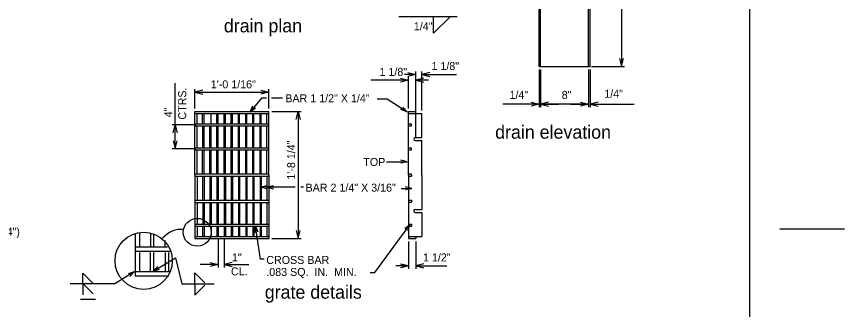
# Model space of a CAD drawing. Extents: x 973.2 to 1069.7, y 1484.4 to 1549.5.
# Drawn here: x 1034.82 to 1069.31, y 1513.03 to 1525.25 of the extents above; entities that cross this region are included whole.
import ezdxf

# ---------------------------------------------------------------- set-up
doc = ezdxf.new("R2010")
doc.units = 0
for name, color, linetype in [('Level 1', 7, 'Continuous'), ('Level 2', 7, 'Continuous'), ('Level 37', 7, 'Continuous')]:
    doc.layers.add(name, color=color, linetype=linetype)

msp = doc.modelspace()

# ---------------------------------------------------------------- linework, layer by layer
at = {"layer": 'Level 1'}
msp.add_line((1065.368, 1488.431), (1065.368, 1544.364), dxfattribs=at)
at = {"layer": 'Level 2'}
for p, q in [((1058.651, 1523.167), (1058.651, 1536.917)), ((1058.713, 1523.17), (1058.713, 1536.917)), ((1056.588, 1523.17), (1056.588, 1535.381)), ((1056.651, 1523.167), (1056.651, 1535.414)), ((1060.017, 1530.323), (1060.017, 1523.167)), ((1050.748, 1525.244), (1053.178, 1525.244)), ((1052.196, 1524.548), (1052.892, 1525.244)), ((1052.196, 1524.548), (1052.196, 1525.212)), ((1051.45, 1520.233), (1051.45, 1522.962)), ((1051.709, 1521.325), (1051.709, 1522.962)), ((1056.588, 1523.17), (1058.713, 1523.17)), ((1056.588, 1523.045), (1056.588, 1521.473)), ((1056.651, 1523.042), (1056.651, 1521.473)), ((1058.651, 1523.042), (1058.651, 1521.473)), ((1058.713, 1523.045), (1058.713, 1521.473)), ((1058.776, 1523.167), (1060.142, 1523.167)), ((1051.147, 1522.591), (1049.575, 1522.591)), ((1051.45, 1522.837), (1050.976, 1522.837)), ((1051.147, 1521.414), (1051.147, 1522.761)), ((1051.976, 1522.591), (1051.45, 1522.591)), ((1051.709, 1522.837), (1053.141, 1522.837)), ((1041.428, 1519.726), (1041.428, 1522.467)), ((1042.251, 1521.414), (1042.251, 1522.22)), ((1045.329, 1521.414), (1045.329, 1522.22)), ((1042.251, 1522.095), (1045.329, 1522.095)), ((1045.022, 1521.85), (1044.551, 1521.277)), ((1045.234, 1521.85), (1045.022, 1521.85)), ((1045.896, 1521.85), (1045.444, 1521.85)), ((1044.551, 1521.277), (1044.666, 1521.519)), ((1049.849, 1521.813), (1050.265, 1521.813)), ((1050.265, 1521.813), (1051.088, 1521.277)), ((1056.588, 1521.597), (1055.08, 1521.597)), ((1058.651, 1521.597), (1056.651, 1521.597)), ((1056.651, 1521.597), (1057.401, 1521.597)), ((1057.901, 1521.597), (1058.651, 1521.597)), ((1058.713, 1521.597), (1060.556, 1521.597)), ((1042.251, 1518.637), (1042.251, 1521.289)), ((1042.251, 1521.289), (1045.329, 1521.289)), ((1042.251, 1521.2), (1045.329, 1521.2)), ((1042.342, 1520.8), (1042.342, 1521.2)), ((1042.566, 1520.8), (1042.566, 1521.2)), ((1042.631, 1520.8), (1042.631, 1521.2)), ((1042.922, 1520.8), (1042.922, 1521.2)), ((1043.166, 1520.8), (1043.166, 1521.2)), ((1043.219, 1520.8), (1043.219, 1521.2)), ((1043.466, 1520.8), (1043.466, 1521.2)), ((1043.522, 1520.8), (1043.522, 1521.2)), ((1043.756, 1520.8), (1043.756, 1521.2)), ((1043.809, 1520.8), (1043.809, 1521.2)), ((1044.062, 1520.8), (1044.062, 1521.2)), ((1044.109, 1520.8), (1044.109, 1521.2)), ((1044.365, 1520.8), (1044.365, 1521.2)), ((1044.409, 1520.8), (1044.409, 1521.2)), ((1044.551, 1521.277), (1044.767, 1521.436)), ((1044.665, 1520.8), (1044.665, 1521.2)), ((1044.703, 1520.8), (1044.703, 1521.2)), ((1044.962, 1520.8), (1044.962, 1521.2)), ((1045.009, 1520.8), (1045.009, 1521.2)), ((1045.248, 1520.8), (1045.248, 1521.2)), ((1045.329, 1518.637), (1045.329, 1521.289)), ((1045.454, 1521.289), (1046.674, 1521.289)), ((1046.548, 1521.289), (1046.548, 1515.985)), ((1051.088, 1521.277), (1050.835, 1521.364)), ((1051.088, 1521.277), (1050.906, 1521.473)), ((1051.147, 1518.637), (1051.147, 1521.289)), ((1051.147, 1521.289), (1051.454, 1521.289)), ((1051.147, 1521.2), (1051.709, 1521.2)), ((1051.454, 1521.2), (1051.454, 1521.289)), ((1051.709, 1520.2), (1051.709, 1521.2)), ((1042.305, 1520.736), (1041.303, 1520.736)), ((1042.251, 1520.776), (1045.329, 1520.776)), ((1042.251, 1520.683), (1045.329, 1520.683)), ((1042.342, 1519.788), (1042.342, 1520.676)), ((1042.572, 1519.788), (1042.572, 1520.676)), ((1042.631, 1519.788), (1042.631, 1520.676)), ((1042.875, 1519.788), (1042.875, 1520.676)), ((1042.922, 1519.788), (1042.922, 1520.676)), ((1043.166, 1519.788), (1043.166, 1520.676)), ((1043.219, 1519.788), (1043.219, 1520.676)), ((1043.466, 1519.788), (1043.466, 1520.676)), ((1043.519, 1519.788), (1043.519, 1520.676)), ((1043.756, 1519.788), (1043.756, 1520.676)), ((1043.809, 1519.788), (1043.809, 1520.676)), ((1044.062, 1519.788), (1044.062, 1520.676)), ((1044.109, 1519.788), (1044.109, 1520.676)), ((1044.365, 1519.788), (1044.365, 1520.676)), ((1044.409, 1519.788), (1044.409, 1520.676)), ((1044.665, 1519.788), (1044.665, 1520.676)), ((1044.703, 1519.788), (1044.703, 1520.676)), ((1044.962, 1519.788), (1044.962, 1520.676)), ((1045.009, 1519.788), (1045.009, 1520.676)), ((1045.248, 1519.788), (1045.248, 1520.676)), ((1051.147, 1520.776), (1051.268, 1520.776)), ((1051.147, 1520.685), (1051.268, 1520.685)), ((1051.268, 1520.685), (1051.268, 1520.776)), ((1042.305, 1520.313), (1042.305, 1520.313)), ((1042.602, 1520.312), (1042.602, 1520.312)), ((1042.9, 1520.311), (1042.9, 1520.311)), ((1043.197, 1520.309), (1043.197, 1520.309)), ((1043.495, 1520.308), (1043.495, 1520.308)), ((1043.792, 1520.307), (1043.792, 1520.307)), ((1044.089, 1520.306), (1044.089, 1520.306)), ((1044.387, 1520.304), (1044.387, 1520.304)), ((1044.684, 1520.303), (1044.684, 1520.303)), ((1044.982, 1520.302), (1044.982, 1520.302)), ((1045.279, 1520.301), (1045.279, 1520.301)), ((1051.434, 1520.2), (1051.709, 1520.2)), ((1042.251, 1519.776), (1045.329, 1519.776)), ((1051.434, 1520.075), (1051.709, 1520.075)), ((1051.709, 1518.637), (1051.709, 1520.075)), ((1042.279, 1519.726), (1041.303, 1519.726)), ((1042.251, 1519.683), (1045.329, 1519.683)), ((1042.342, 1518.708), (1042.342, 1519.676)), ((1042.566, 1518.708), (1042.566, 1519.676)), ((1042.631, 1518.708), (1042.631, 1519.676)), ((1042.875, 1518.708), (1042.875, 1519.676)), ((1042.922, 1518.708), (1042.922, 1519.676)), ((1043.166, 1518.708), (1043.166, 1519.676)), ((1043.219, 1518.708), (1043.219, 1519.676)), ((1043.466, 1518.708), (1043.466, 1519.676)), ((1043.519, 1518.708), (1043.519, 1519.676)), ((1043.756, 1518.708), (1043.756, 1519.676)), ((1043.809, 1518.708), (1043.809, 1519.676)), ((1044.062, 1518.708), (1044.062, 1519.676)), ((1044.109, 1518.708), (1044.109, 1519.676)), ((1044.365, 1518.708), (1044.365, 1519.676)), ((1044.409, 1518.708), (1044.409, 1519.676)), ((1044.665, 1518.708), (1044.665, 1519.676)), ((1044.703, 1518.708), (1044.703, 1519.676)), ((1044.962, 1518.708), (1044.962, 1519.676)), ((1045.009, 1518.708), (1045.009, 1519.676)), ((1045.248, 1518.708), (1045.248, 1519.676)), ((1051.147, 1519.768), (1051.268, 1519.768)), ((1051.147, 1519.692), (1051.268, 1519.692)), ((1051.268, 1519.692), (1051.268, 1519.768)), ((1050.232, 1519.191), (1051.09, 1519.191)), ((1051.09, 1519.191), (1050.83, 1519.256)), ((1051.09, 1519.191), (1050.83, 1519.126)), ((1042.251, 1518.683), (1045.329, 1518.683)), ((1042.251, 1518.637), (1042.251, 1515.985)), ((1042.251, 1518.592), (1045.329, 1518.592)), ((1042.342, 1518.567), (1042.342, 1517.598)), ((1042.566, 1518.567), (1042.566, 1517.598)), ((1042.631, 1518.567), (1042.631, 1517.598)), ((1042.875, 1518.567), (1042.875, 1517.598)), ((1042.922, 1518.567), (1042.922, 1517.598)), ((1043.166, 1518.567), (1043.166, 1517.598)), ((1043.219, 1518.567), (1043.219, 1517.598)), ((1043.466, 1518.567), (1043.466, 1517.598)), ((1043.519, 1518.567), (1043.519, 1517.598)), ((1043.756, 1518.567), (1043.756, 1517.598)), ((1043.809, 1518.567), (1043.809, 1517.598)), ((1044.062, 1518.567), (1044.062, 1517.598)), ((1044.109, 1518.567), (1044.109, 1517.598)), ((1044.365, 1518.567), (1044.365, 1517.598)), ((1044.409, 1518.567), (1044.409, 1517.598)), ((1044.665, 1518.567), (1044.665, 1517.598)), ((1044.703, 1518.567), (1044.703, 1517.598)), ((1044.962, 1518.567), (1044.962, 1517.598)), ((1045.009, 1518.567), (1045.009, 1517.598)), ((1045.248, 1518.567), (1045.248, 1517.598)), ((1045.329, 1518.637), (1045.329, 1515.985)), ((1051.147, 1518.683), (1051.268, 1518.683)), ((1051.147, 1518.637), (1051.147, 1515.985)), ((1051.147, 1518.592), (1051.268, 1518.592)), ((1051.268, 1518.637), (1051.268, 1518.683)), ((1051.268, 1518.637), (1051.268, 1518.592)), ((1051.709, 1518.637), (1051.709, 1517.199)), ((1044.998, 1518.148), (1045.262, 1518.194)), ((1045.259, 1518.129), (1044.998, 1518.148)), ((1044.998, 1518.148), (1045.253, 1518.065)), ((1045.259, 1518.129), (1045.519, 1518.194)), ((1045.259, 1518.129), (1045.519, 1518.064)), ((1046.432, 1518.129), (1045.259, 1518.129)), ((1046.773, 1518.129), (1046.656, 1518.129)), ((1050.847, 1518.08), (1051.286, 1518.08)), ((1051.286, 1518.08), (1051.026, 1518.145)), ((1051.286, 1518.08), (1051.026, 1518.015)), ((1042.251, 1517.592), (1045.329, 1517.592)), ((1042.251, 1517.498), (1045.329, 1517.498)), ((1042.342, 1517.486), (1042.342, 1516.599)), ((1042.572, 1517.486), (1042.572, 1516.599)), ((1042.631, 1517.486), (1042.631, 1516.599)), ((1042.875, 1517.486), (1042.875, 1516.599)), ((1042.922, 1517.486), (1042.922, 1516.599)), ((1043.166, 1517.486), (1043.166, 1516.599)), ((1043.219, 1517.486), (1043.219, 1516.599)), ((1043.466, 1517.486), (1043.466, 1516.599)), ((1043.519, 1517.486), (1043.519, 1516.599)), ((1043.756, 1517.486), (1043.756, 1516.599)), ((1043.809, 1517.486), (1043.809, 1516.599)), ((1044.062, 1517.486), (1044.062, 1516.599)), ((1044.109, 1517.486), (1044.109, 1516.599)), ((1044.365, 1517.486), (1044.365, 1516.599)), ((1044.409, 1517.486), (1044.409, 1516.599)), ((1044.665, 1517.486), (1044.665, 1516.599)), ((1044.703, 1517.486), (1044.703, 1516.599)), ((1044.962, 1517.486), (1044.962, 1516.599)), ((1045.009, 1517.486), (1045.009, 1516.599)), ((1045.248, 1517.486), (1045.248, 1516.599)), ((1051.147, 1517.583), (1051.268, 1517.583)), ((1051.147, 1517.506), (1051.268, 1517.506)), ((1051.268, 1517.583), (1051.268, 1517.506)), ((1051.434, 1517.2), (1051.709, 1517.2)), ((1051.434, 1517.075), (1051.709, 1517.075)), ((1051.709, 1517.074), (1051.709, 1516.075)), ((1042.305, 1516.961), (1042.305, 1516.961)), ((1042.602, 1516.962), (1042.602, 1516.962)), ((1042.9, 1516.964), (1042.9, 1516.964)), ((1043.197, 1516.965), (1043.197, 1516.965)), ((1043.495, 1516.966), (1043.495, 1516.966)), ((1043.792, 1516.967), (1043.792, 1516.967)), ((1044.089, 1516.969), (1044.089, 1516.969)), ((1044.387, 1516.97), (1044.387, 1516.97)), ((1044.684, 1516.971), (1044.684, 1516.971)), ((1044.982, 1516.972), (1044.982, 1516.972)), ((1045.279, 1516.974), (1045.279, 1516.974)), ((1042.251, 1516.592), (1045.329, 1516.592)), ((1042.251, 1516.498), (1045.329, 1516.498)), ((1042.342, 1516.474), (1042.342, 1516.075)), ((1042.566, 1516.474), (1042.566, 1516.075)), ((1042.631, 1516.474), (1042.631, 1516.075)), ((1042.922, 1516.474), (1042.922, 1516.075)), ((1043.166, 1516.474), (1043.166, 1516.075)), ((1043.219, 1516.474), (1043.219, 1516.075)), ((1043.466, 1516.474), (1043.466, 1516.075)), ((1043.522, 1516.474), (1043.522, 1516.075)), ((1043.756, 1516.474), (1043.756, 1516.075)), ((1043.809, 1516.474), (1043.809, 1516.075)), ((1044.062, 1516.474), (1044.062, 1516.075)), ((1044.109, 1516.474), (1044.109, 1516.075)), ((1044.365, 1516.474), (1044.365, 1516.075)), ((1044.409, 1516.474), (1044.409, 1516.075)), ((1044.665, 1516.474), (1044.665, 1516.075)), ((1044.703, 1516.474), (1044.703, 1516.075)), ((1044.775, 1516.509), (1044.748, 1516.242)), ((1044.975, 1515.131), (1044.775, 1516.509)), ((1044.775, 1516.509), (1044.876, 1516.261)), ((1044.962, 1516.474), (1044.962, 1516.075)), ((1045.009, 1516.474), (1045.009, 1516.075)), ((1045.248, 1516.474), (1045.248, 1516.075)), ((1049.743, 1514.566), (1051.2, 1516.565)), ((1051.2, 1516.565), (1050.995, 1516.393)), ((1051.2, 1516.565), (1051.1, 1516.316)), ((1051.147, 1516.589), (1051.268, 1516.589)), ((1051.147, 1516.498), (1051.268, 1516.498)), ((1051.268, 1516.589), (1051.268, 1516.498)), ((1039.759, 1516.188), (1039.759, 1514.432)), ((1039.942, 1516.244), (1039.942, 1515.659)), ((1040.402, 1516.197), (1040.402, 1515.659)), ((1040.52, 1516.16), (1040.52, 1515.659)), ((1042.251, 1516.075), (1045.329, 1516.075)), ((1042.251, 1515.985), (1045.329, 1515.985)), ((1045.454, 1515.985), (1046.674, 1515.985)), ((1051.147, 1516.075), (1051.709, 1516.075)), ((1051.147, 1515.985), (1051.454, 1515.985)), ((1051.454, 1516.075), (1051.454, 1515.985)), ((1039.759, 1515.645), (1041.101, 1515.645)), ((1040.989, 1515.908), (1040.989, 1515.659)), ((1043.219, 1515.95), (1043.219, 1514.786)), ((1043.466, 1515.95), (1043.466, 1514.786)), ((1051.147, 1515.86), (1051.147, 1514.721)), ((1051.45, 1515.86), (1051.45, 1514.721)), ((1039.759, 1515.458), (1041.259, 1515.458)), ((1039.942, 1515.41), (1039.942, 1514.611)), ((1040.389, 1515.41), (1040.389, 1514.611)), ((1040.52, 1515.41), (1040.52, 1514.611)), ((1041.008, 1515.41), (1041.008, 1514.611)), ((1041.148, 1515.41), (1041.148, 1514.611)), ((1040.514, 1514.633), (1041.436, 1515.182)), ((1041.436, 1515.182), (1041.706, 1514.092)), ((1045.137, 1515.131), (1044.975, 1515.131)), ((1039.723, 1514.605), (1038.913, 1514.092)), ((1039.723, 1514.605), (1039.468, 1514.521)), ((1039.723, 1514.605), (1039.538, 1514.411)), ((1039.759, 1514.611), (1041.231, 1514.611)), ((1040.514, 1514.633), (1040.704, 1514.821)), ((1040.514, 1514.633), (1040.771, 1514.71)), ((1043.219, 1514.911), (1042.469, 1514.911)), ((1043.466, 1514.911), (1044.498, 1514.911)), ((1051.147, 1514.846), (1050.615, 1514.846)), ((1051.147, 1514.846), (1050.887, 1514.911)), ((1051.147, 1514.846), (1050.887, 1514.781)), ((1051.45, 1514.846), (1052.744, 1514.846)), ((1037.581, 1514.092), (1037.581, 1514.54)), ((1037.581, 1514.54), (1037.996, 1514.125)), ((1039.759, 1514.432), (1041.092, 1514.432)), ((1042.246, 1514.111), (1042.246, 1514.558)), ((1042.246, 1514.558), (1042.662, 1514.143)), ((1049.55, 1514.566), (1049.743, 1514.566)), ((1038.913, 1514.092), (1037.049, 1514.092)), ((1037.581, 1514.092), (1037.581, 1513.645)), ((1037.59, 1514.093), (1038.006, 1513.678)), ((1041.706, 1514.092), (1043.047, 1514.092)), ((1042.246, 1514.074), (1042.246, 1513.626)), ((1042.246, 1513.626), (1042.662, 1514.042)), ((1037.488, 1513.459), (1038.103, 1513.459))]:
    msp.add_line(p, q, dxfattribs=at)
for points in [[(1059.934, 1523.5), (1060.017, 1523.167), (1060.101, 1523.5)], [(1051.117, 1522.92), (1051.45, 1522.837), (1051.117, 1522.753)], [(1052.042, 1522.92), (1051.709, 1522.837), (1052.042, 1522.753)], [(1050.813, 1522.674), (1051.147, 1522.591), (1050.813, 1522.507)], [(1051.783, 1522.674), (1051.45, 1522.591), (1051.783, 1522.507)], [(1042.584, 1522.178), (1042.251, 1522.095), (1042.584, 1522.011)], [(1044.995, 1522.178), (1045.329, 1522.095), (1044.995, 1522.011)], [(1056.255, 1521.681), (1056.588, 1521.597), (1056.255, 1521.514)], [(1056.984, 1521.681), (1056.651, 1521.597), (1056.984, 1521.514)], [(1058.317, 1521.681), (1058.651, 1521.597), (1058.317, 1521.514)], [(1059.047, 1521.681), (1058.713, 1521.597), (1059.047, 1521.514)], [(1046.465, 1520.956), (1046.548, 1521.289), (1046.632, 1520.956)], [(1041.344, 1520.403), (1041.428, 1520.736), (1041.511, 1520.403)], [(1041.344, 1520.059), (1041.428, 1519.726), (1041.511, 1520.059)], [(1046.465, 1516.318), (1046.548, 1515.985), (1046.632, 1516.318)], [(1042.885, 1514.994), (1043.219, 1514.911), (1042.885, 1514.827)], [(1043.799, 1514.994), (1043.466, 1514.911), (1043.799, 1514.827)], [(1050.813, 1514.93), (1051.147, 1514.846), (1050.813, 1514.763)], [(1051.783, 1514.93), (1051.45, 1514.846), (1051.783, 1514.763)]]:
    msp.add_lwpolyline(points, dxfattribs=at)
for centre, radius in [((1042.344, 1516.248), 0.581), ((1040.114, 1515.061), 1.193)]:
    msp.add_circle(centre, radius, dxfattribs=at)
for centre, radius, start, end in [((1051.434, 1520.137), 0.0625, 90, 270), ((1051.434, 1517.137), 0.0625, 90, 270), ((1041.684, 1515.363), 1.007, 83.9792, 140.6583)]:
    msp.add_arc(centre, radius, start, end, dxfattribs=at)
at = {"layer": 'Level 37'}
msp.add_line((1066.62, 1516.397), (1069.311, 1516.397), dxfattribs=at)

# ---------------------------------------------------------------- texts
at = {"layer": 'Level 2'}
for s, height, p in [('drain plan', 0.555, (1043.455, 1524.588)), ('1/4"', 0.3333, (1051.37, 1524.674)), ('1 1/8"', 0.3333, (1052.106, 1523.018)), ('1 1/8"', 0.3333, (1049.94, 1522.772)), ('1\'-0 1/16"', 0.3333, (1042.91, 1522.254)), (' 1/4"', 0.3333, (1059.181, 1521.858)), ('BAR 1 1/2" X 1/4"', 0.33333, (1046.015, 1521.671)), (' 1/4"', 0.3333, (1055.232, 1521.812)), ('8"', 0.3333, (1057.531, 1521.812)), ('drain elevation', 0.555, (1054.757, 1520.153)), ('TOP', 0.3333, (1049.267, 1519.015)), ('BAR 2 1/4" X 3/16"', 0.33333, (1046.858, 1517.944)), ('(OR CUT FROM L 2" X 2" X 1/4")', 0.33333, (1028.339, 1516.107)), (' 1"', 0.3333, (1043.669, 1515.036)), ('1 1/2"', 0.3333, (1051.753, 1515.033)), ('CROSS BAR', 0.3333, (1045.223, 1514.928)), ('CL.', 0.3333, (1043.751, 1514.452)), ('.083 SQ.  IN.  MIN.', 0.33333, (1045.223, 1514.428)), ('grate details', 0.555, (1045.159, 1513.479))]:
    msp.add_text(s, height=height, dxfattribs=at).set_placement(p)
for s, p in [('CTRS.', (1041.886, 1520.949)), ('4"', (1041.303, 1521.042)), ('1\'-8 1/4"', (1046.424, 1518.446))]:
    msp.add_text(s, height=0.3333, rotation=90, dxfattribs=at).set_placement(p)

doc.saveas('drawing.dxf')
